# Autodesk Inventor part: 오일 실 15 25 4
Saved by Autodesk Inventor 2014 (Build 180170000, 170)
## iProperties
Created: 2025-06
Part Number: 오일 실 15 25 4
Material: 고무
Document SubType Name: Modeling
Designer: dg
Density: 0.93 g/cm^3
Appearance: 고무 - 검은색 - 버전 1.1
Mass: 0.725012 g
Surface Area: 12.9385 cm^2
Volume: 0.779583 cm^3
Author: jhkim
Description: 오일 실 - 비스프링, 조립 GA
Creation Date: 2025-05-27
Sending System: Autodesk Inventor 2026
Preprocessor: ST-DEVELOPER v20.1
Author: dg
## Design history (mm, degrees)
node "오일 실 15 25 41"
body "Solid1"
node "기준1"
